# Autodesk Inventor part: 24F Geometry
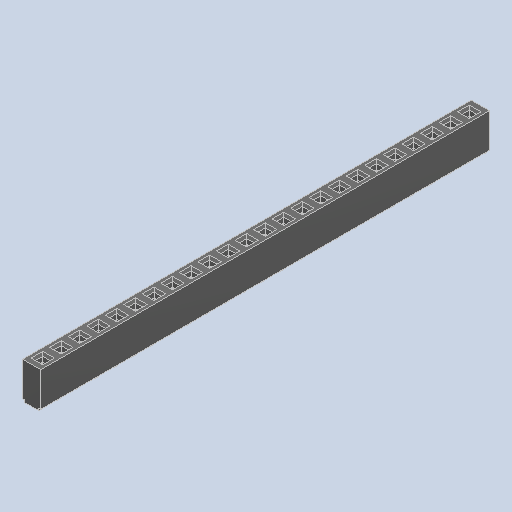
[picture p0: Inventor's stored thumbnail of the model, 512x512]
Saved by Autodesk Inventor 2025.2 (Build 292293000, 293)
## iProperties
Created: 2025-04
Part Number: 24F Geometry
Material: Generic
Description: PART-24F Geometry-DESC
Document SubType Name: Modeling
Designer: BennF
Density: 1 g/cm^3
Appearance: Default
Author: BennF
Revision Number: NONE
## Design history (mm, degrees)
feature "Solid"
body "Solid1"
